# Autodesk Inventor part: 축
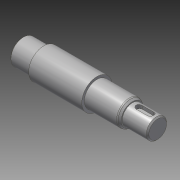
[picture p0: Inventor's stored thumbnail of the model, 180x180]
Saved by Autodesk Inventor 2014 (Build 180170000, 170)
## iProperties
Created: 2016-06
Part Number: 축
Material: 강철, 연강
Document SubType Name: Modeling
Designer: mduedu
Density: 7.86 g/cm^3
Appearance: Steel
Author: mduedu
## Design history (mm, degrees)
sketch "스케치1"
  geometry: L1 (-53.5, 0)-(53.5, 0); L2 (-53.5, 0)-(-53.5, 10); L3 (-53.5, 10)-(-36.5, 10); L4 (-36.5, 10)-(-36.5, 12); L5 (-36.5, 12)-(5.5, 12); L6 (5.5, 12)-(5.5, 10); L7 (5.5, 10)-(33.5, 10); L8 (33.5, 10)-(33.5, 8); L9 (33.5, 8)-(53.5, 8); L10 (53.5, 8)-(53.5, 0); 2 further points
  constraints: 20 end point, 5 parallel, 2 perpendicular, 1 coincident, 1 collinear, 1 horizontal, 1 midpoint, 1 vertical
  dimensions: "d0" = 107 distance of L1.start L1.end; "d2" = 16 diameter of L9 L1; "d3" = 20 diameter of L7 L1; "d4" = 24 diameter of L5 L1; "d5" = 20 diameter of L3 L1; "d6" = 17 distance of L2.end L3.end; "d7" = 20 distance of L8.end L9.end; "d8" = 48 distance from line of L5.end L10
revolve "회전1" sketch "스케치1" stored, may be unused: angle "d9" = 90 deg
chamfer "모따기1" distance "d10" = 2; stored, may be unused: second distance "d11" = 2, angle "d12" = 30 deg
fillet "모깎기1" dims "d13" = 2
node "작업 평면1"
sketch "스케치2"
  geometry: L1 (-4.5, 2.5)-(4.5, 2.5); L2 (4.5, -2.5)-(-4.5, -2.5); L3 (-4.5, 0)-(4.5, 0); L4 (-10, 8.845)-(-10, -8.845) reference; A1 r 2.5 centre (-4.5, 0) between (-4.5, 2.5) and (-4.5, -2.5); A2 r 2.5 centre (4.5, 0) between (4.5, -2.5) and (4.5, 2.5); 1 further point
  constraints: 6 end point, 4 point on circle, 3 tangent, 2 centre point, 2 parallel, 1 horizontal, 1 horizontal alignment
  dimensions: "d14" = 3 distance edge to line of A1 L4; "d15" = 5 distance between parallel lines of L2 L1; "d16" = 14 dimension on A2 A1
extrude "돌출1" cut sketch "스케치2" distance "d17" = 3; taper "d18" = 0 deg
chamfer "모따기2" distance "d19" = 1; stored, may be unused: second distance "d20" = 2, angle "d21" = 30 deg
sketch "스케치3"
  geometry: L1 (-33.5, -8)-(-52.5, -8) reference; L2 (-53.5, -7)-(-53.5, 7) reference; L3 (-36, -8)-(-37.5, -6.5); L4 (-37.5, -6.5)-(-37.5, -8); L5 (-36, -8)-(-37.5, -8); 1 further point
  constraints: 6 end point, 2 point on line, 1 collinear, 1 vertical
  dimensions: "d22" = 45 deg angle of L4 L3; "d23" = 16 distance between parallel lines of L2 L4; "d24" = 3 diameter of L3.start L4
revolve "회전2" stored, may be unused: angle "d25" = 90 deg
node "작업점1"
sketch "스케치4"
  geometry: 1 further point
hole "구멍1" sketch "스케치4" at (0, 0) diameter "d26" = 3.242; stored, may be unused: countersink angle "d30" = 90 deg, drill point angle "d32" = 120 deg; dims "d27" = 8, "d28" = 4, "d29" = 2, "d31" = 11
chamfer "모따기3" distance "d33" = 2; stored, may be unused: second distance "d34" = 2, angle "d35" = 30 deg
node "솔리드1"
